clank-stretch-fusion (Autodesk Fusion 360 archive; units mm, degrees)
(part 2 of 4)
sketch "Profile" plane through (3.2, 0, 0) normal (1, 0, 0) x axis (0, 1, 0)
  line L1 (9, 202.17) -> (9, -2.17)
  line L2 (6.5, 202.17) -> (9, 202.17)
  line L3 (6.5, -2.17) -> (6.5, 202.17)
  line L4 (9, -2.17) -> (6.5, -2.17)
  line L5 (8, 15.83) -> (8, 233.17)
  line L6 (6.874, 15.83) -> (6.874, 233.17)
  line L7 (8.254, 233.17) -> (8.254, 15.83)
  line L8 (7.624, 233.17) -> (7.624, 15.83)
  line L9 (7.624, 16.83) -> (6.5, 16.83)
  line L10 (9, 15.83) -> (6.5, 15.83)
  line L11 (8.254, 233.17) -> (6.874, 233.17)
  line L12 (8.154, -2.17) -> (8.154, 31.83)
  line L13 (7.904, -2.17) -> (7.904, 15.83)
  line L14 (14.5, 31.83) -> (8.154, 31.83)
  line L15 (14.5, -2.17) -> (14.5, 31.83)
  line L16 (9, -2.17) -> (14.5, -2.17)
  line L17 (14.5, 217.17) -> (0, 217.17)
  line L18 (0, 217.17) -> (0, 202.17)
  line L19 (6.5, 202.17) -> (0, 202.17)
  line L20 (6.5, 217.17) -> (6.5, 202.17)
  line L21 (14.5, 233.17) -> (14.5, 217.17)
  line L22 (8.154, 233.17) -> (14.5, 233.17)
  line L23 (8.154, 217.17) -> (8.154, 233.17)
  line L24 (0, 233.17) -> (8.154, 233.17)
  line L25 (0, 217.17) -> (0, 233.17)
  line L26 (0, 218.17) -> (7.624, 218.17)
  line L27 (7.624, 251.17) -> (7.624, 233.17)
  line L28 (0, 251.17) -> (7.624, 251.17)
  line L29 (0, 233.17) -> (0, 251.17)
  line L30 (8.154, 251.17) -> (8.154, 233.17)
  line L31 (14.5, 251.17) -> (8.154, 251.17)
  line L32 (14.5, 233.17) -> (14.5, 251.17)
  line L33 (7.874, 251.17) -> (7.874, 217.17)
  line L34 (8.154, 251.17) -> (7.874, 251.17)
  line L35 (0, 216.92) -> (6.5, 216.92)
  arc A1 centre (7.424, 15.83) radius 0.55 clockwise from (6.874, 15.83) to (7.172, 16.3189)
  arc A2 centre (7.6302, 15.43) radius 1 clockwise from (7.172, 16.3189) to (7.4944, 16.4207)
  arc A3 centre (7.474, 16.5693) radius 0.15 clockwise from (7.624, 16.5693) to (7.4944, 16.4207)
  arc A4 centre (7.424, 217.17) radius 0.55 clockwise from (6.874, 217.17) to (7.172, 217.6589)
  arc A5 centre (7.6302, 216.77) radius 1 clockwise from (7.172, 217.6589) to (7.4944, 217.7607)
  arc A6 centre (7.474, 217.9093) radius 0.15 clockwise from (7.624, 217.9093) to (7.4944, 217.7607)
  point P15 (6.874, 15.83)
  point P18 (7.624, 16.5693)
  point P22 (6.5, 16.83)
  point P23 (7.624, 16.83)
  point P24 (6.5, 15.83)
  point P25 (9, 15.83)
  point P10 (6.874, 15.83)
  point P13 (7.424, 15.83)
  point P20 (7.624, 15.83)
  point P7 (8, 15.83)
  point P11 (8.254, 15.83)
  point P12 (8.254, 233.17)
  point P26 (8.254, 233.17)
  point P6 (8, 233.17)
  point P21 (7.624, 233.17)
  point P29 (7.904, 15.83)
  point P30 (7.904, -2.17)
  point P2 (9, -2.17)
  point P33 (9, -2.17)
  point P28 (8.154, -2.17)
  point P27 (8.154, 31.83)
  point P36 (8.154, 31.83)
  point P37 (0, 202.17)
  point P38 (0, 202.17)
  point P40 (0, 202.17)
  point P4 (6.5, 202.17)
  point P41 (6.5, 202.17)
  point P42 (6.5, 217.17)
  point P34 (0, 217.17)
  point P39 (0, 217.17)
  point P45 (8.154, 217.17)
  point P47 (0, 217.17)
  point P31 (14.5, 31.83)
  point P53 (6.874, 217.17)
  point P52 (7.424, 217.17)
  point P49 (7.624, 217.9093)
  point P55 (7.624, 218.17)
  point P56 (0, 218.17)
  point P46 (0, 233.17)
  point P59 (0, 233.17)
  point P43 (14.5, 233.17)
  point P62 (14.5, 233.17)
  point P60 (8.154, 251.17)
  point P63 (7.874, 217.17)
  point P65 (6.5, 216.92)
  point P66 (0, 216.92)
  point P16 (7.6302, 15.43)
  point P32 (14.5, -2.17)
  point P3 (9, 202.17)
  point P48 (7.6302, 216.77)
  point P61 (14.5, 251.17)
  point P57 (7.624, 251.17)
  point P64 (7.874, 251.17)
  perpendicular L4 L5
  perpendicular L4 L6
  perpendicular L4 L7
  coincident L6 P15
  tangent A1 A2
  tangent A2 A3
  vertical L8
  coincident P18 L8
  tangent A3 L8
  coincident L3 P22
  coincident L8 P23
  perpendicular L8 L9
  coincident L3 P24
  coincident L1 P25
  perpendicular L1 L10
  coincident P10 L10
  coincident P15 L10
  coincident P13 L10
  coincident P20 L10
  coincident P7 L10
  coincident P11 L10
  perpendicular L5 L11
  coincident P12 P26
  coincident P6 L11
  coincident P21 L11
  perpendicular L10 L12
  coincident L10 P29
  coincident L4 P30
  perpendicular L4 L13
  perpendicular L7 L14
  perpendicular L14 L15
  perpendicular L15 L16
  coincident P2 P33
  coincident L4 P28
  horizontal L17
  coincident P27 P36
  coincident P37 P38
  parallel L8 L18
  coincident P37 P40
  coincident P4 P41
  perpendicular L19 L20
  coincident L17 P42
  coincident P34 P39
  perpendicular L17 L21
  perpendicular L21 L22
  coincident L17 P45
  perpendicular L17 L23
  perpendicular L8 L24
  perpendicular L24 L25
  coincident P39 P47
  coincident P31 L21
  coincident P12 L22
  coincident P27 L23
  tangent A4 A5
  tangent A5 A6
  coincident L17 P53
  coincident L17 P52
  coincident L8 P49
  coincident L6 P53
  tangent L8 A6
  coincident L8 P55
  coincident L25 P56
  perpendicular L25 L26
  perpendicular L24 L27
  perpendicular L27 L28
  perpendicular L28 L29
  coincident P46 P59
  perpendicular L22 L30
  perpendicular L30 L31
  perpendicular L22 L32
  coincident P43 P62
  coincident L28 P60
  coincident L17 P63
  perpendicular L31 L33
  perpendicular L30 L34
  coincident L20 P65
  coincident L18 P66
  perpendicular L18 L35
  dimension "d100" distance L1 L5 = 1
  dimension "d102" distance P7 P11 = 0.254
  dimension "d103" distance P10 P11 = 1.38
  dimension "d104" radius A1 = 0.55
  dimension "d106" radius A2 = 1
  dimension "d107" radius A3 = 0.15
  dimension "d109" distance L6 P21 = 0.75
  dimension "d110" distance P13 L9 = 1
  dimension "d149" distance P16 L10 = 0.4
  dimension "d150" distance P2 L10 = 18
  dimension "d155" distance P11 L12 = 0.1
  dimension "d156" distance P32 P33 = 5.5
  dimension "d174" distance P28 L13 = 0.25
  dimension "d175" distance P28 L15 = 6.346
  dimension "d179" distance P3 L17 = 15
  dimension "d180" distance P25 L14 = 16
  dimension "d190" distance P12 L17 = 16
  dimension "d193" radius A4 = 0.55
  dimension "d194" radius A5 = 1
  dimension "d195" radius A6 = 0.15
  dimension "d196" distance L17 P48 = 0.4
  dimension "d197" distance P53 L26 = 1
  dimension "d225" distance P61 P62 = 18
  dimension "d250" distance P57 P64 = 0.25
  dimension "d261" distance P47 L35 = 0.25
extrude "Extrude12" new body sketch "Profile" profile of L3 A1 A2 A3 L8 L9 to an object
mirror "Mirror3" mirrorStitchTolerance 0.1
rectangular_pattern "R-Pattern1" uSpaceDistance 2 vSpaceDistance 0
combine "Combine1"
extrude "Extrude15" add sketch "Profile" profile of L3 L4 L10 L13 to an object
extrude "Extrude16" new body sketch "Profile" profile of L1 L4 L10 L12 L14 L15 L16 to an object offset -0.25 from offset 0.25 bodies "XZ Lower Clamp"
chamfer "Chamfer1" distance 2.5
chamfer "Chamfer9" distance 12 distance 3
sketch "Lower Pinch Nuts" plane through (0, 14.5, 0) normal (0, 1, 0) x axis (-1, 0, 0)
  line L1 (-14.95, -2.17) -> (-14.95, 19.83)
  line L2 (-5.95, -2.17) -> (-14.95, -2.17)
  line L3 (-5.95, 19.83) -> (-5.95, -2.17)
  line L4 (-6.4085, 11.83) -> (-8.4293, 8.33)
  line L5 (-8.4293, 15.33) -> (-6.4085, 11.83)
  line L6 (-12.4707, 15.33) -> (-8.4293, 15.33)
  line L7 (-14.4915, 11.83) -> (-12.4707, 15.33)
  line L8 (-12.4707, 8.33) -> (-14.4915, 11.83)
  line L9 (-8.4293, 8.33) -> (-12.4707, 8.33)
  line L10 (-6.4085, 2.83) -> (-8.4293, -0.67)
  line L11 (-8.4293, 6.33) -> (-6.4085, 2.83)
  line L12 (-12.4707, 6.33) -> (-8.4293, 6.33)
  line L13 (-14.4915, 2.83) -> (-12.4707, 6.33)
  line L14 (-12.4707, -0.67) -> (-14.4915, 2.83)
  line L15 (-8.4293, -0.67) -> (-12.4707, -0.67)
  line L16 (-10.45, 2.83) -> (-10.45, -2.17)
  line L17 (-10.45, 2.83) -> (-10.45, 11.83)
  line L18 (-14.95, 19.83) -> (-5.95, 19.83)
  circle C1 centre (-10.45, 11.83) radius 2.125
  circle C2 centre (-10.45, 2.83) radius 2.125
  circle C3 centre (-10.45, 11.83) radius 4.125
  circle C4 centre (-10.45, 2.83) radius 4.125
  point P6 (-10.45, 11.83)
  point P13 (-10.45, 11.83)
  point P20 (-10.45, 2.83)
  point P21 (-10.45, 2.83)
  point P22 (-10.45, -2.17)
  point P23 (-10.45, 2.83)
  point P24 (-10.45, 11.83)
  point P25 (-10.45, 2.83)
  point P26 (-10.45, 11.83)
  point P14 (-8.4293, -0.67)
  coincident P6 P13
  coincident P20 P21
  midpoint L2 P22
  coincident P21 P23
  vertical L16
  horizontal L15
  equal C1 C2
  equal L9 L15
  horizontal L9
  coincident P6 P24
  coincident P20 P25
  vertical L17
  coincident P13 P26
  concentric C2 C4
  equal C3 C4
  dimension "d163" distance P14 L12 = 7
  dimension "d164" diameter C2 = 4.25
  dimension "d165" distance P22 P23 = 5
  dimension "d166" distance P24 P25 = 9
  dimension "d177" diameter C3 = 8.25
extrude "Extrude17" cut sketch "Lower Pinch Nuts" profile of C1 C2 to an object
extrude "Extrude19" cut sketch "Lower Pinch Nuts" profile of C1 L4 L5 L6 L7 L8 L9 L10 L11 L12 L13 L14 L15 C2 against normal blind 5.2
chamfer "Chamfer2" distance 0.4
chamfer "Chamfer3" distance 2.5
extrude "Extrude21" sketch "Profile" profile of L8 L17 L25 A4 A5 A6 L26 to an object bodies "XZ Upper Clamp Front"
mirror "Mirror4" mirrorStitchTolerance 0.1
rectangular_pattern "R-Pattern2" uSpaceDistance 2 vSpaceDistance 0
combine "Combine2"
extrude "Extrude28" add sketch "Profile" profile of L24 L27 L28 L29 to an object
extrude "Extrude29" new body sketch "Profile" profile of L17 L21 L22 L23 L24 L30 L31 L32 L33 L34 to an object bodies "XZ Upper Clamp Rear"
sketch "Sketch6" plane through (0, 14.5, 0) normal (0, 1, 0) x axis (-1, 0, 0)
  line L1 (-17.7, 217.17) -> (-17.7, 251.17)
  line L2 (-3.2, 217.17) -> (-17.7, 217.17)
  line L3 (-3.2, 251.17) -> (-3.2, 217.17)
  line L4 (-17.7, 251.17) -> (-3.2, 251.17)
  line L5 (-8.4293, 242.67) -> (-12.4707, 242.67)
  line L6 (-12.4707, 242.67) -> (-14.4915, 246.17)
  line L7 (-8.4293, 233.67) -> (-12.4707, 233.67)
  line L8 (-12.4707, 233.67) -> (-14.4915, 237.17)
  line L9 (-12.4707, 240.67) -> (-8.4293, 240.67)
  line L10 (-8.4293, 249.67) -> (-6.4085, 246.17)
  line L11 (-14.4915, 237.17) -> (-12.4707, 240.67)
  line L12 (-6.4085, 237.17) -> (-8.4293, 233.67)
  line L13 (-8.4293, 240.67) -> (-6.4085, 237.17)
  line L14 (-14.4915, 246.17) -> (-12.4707, 249.67)
  line L15 (-6.4085, 246.17) -> (-8.4293, 242.67)
  line L16 (-12.4707, 249.67) -> (-8.4293, 249.67)
  line L17 (-10.45, 237.17) -> (-10.45, 246.17)
  line L18 (-10.45, 251.17) -> (-10.45, 246.17)
  circle C1 centre (-10.45, 237.17) radius 4.125
  circle C2 centre (-10.45, 237.17) radius 2.125
  circle C3 centre (-10.45, 246.17) radius 4.125
  circle C4 centre (-10.45, 246.17) radius 2.125
  point P6 (-10.45, 246.17)
  point P12 (-10.45, 246.17)
  point P16 (-10.45, 237.17)
  point P24 (-10.45, 237.17)
  point P25 (-10.45, 237.17)
  point P26 (-10.45, 246.17)
  point P23 (-10.45, 237.17)
  point P15 (-10.45, 246.17)
  point P27 (-10.45, 246.17)
  point P28 (-10.45, 251.17)
  point P19 (-8.4293, 233.67)
  coincident P6 P12
  coincident P16 P24
  coincident P24 P25
  horizontal L7
  equal C2 C4
  equal L5 L7
  horizontal L5
  coincident P6 P26
  coincident P16 P23
  vertical L17
  coincident P12 P15
  concentric C1 C2
  equal C1 C3
  coincident P15 P27
  midpoint L4 P28
  vertical L18
  dimension "d230" distance P19 L9 = 7
  dimension "d231" diameter C2 = 4.25
  dimension "d232" distance P23 P26 = 9
  dimension "d233" diameter C3 = 8.25
  dimension "d234" distance P27 P28 = 5
extrude "Extrude30" cut sketch "Sketch6" profile of C2 C4 to an object
extrude "Extrude31" cut sketch "Sketch6" profile of L5 L6 L7 L8 L9 L10 C2 L11 C4 L12 L13 L14 L15 L16 to an object
chamfer "Chamfer5" distance 2.25
chamfer "Chamfer6" distance 0.5
extrude "Extrude32" sketch "Profile" profile of L8 L17 L21 L22 L23 L24 L25 A4 A5 A6 L26 L27 L28 L29 L30 L31 L32 L33 L34 blind 9
extrude "Extrude33" add sketch "Profile" profile of L8 L17 L21 L22 L23 L24 L25 A4 A5 A6 L26 L27 L28 L29 L30 L31 L32 L33 L34 against normal blind 9
sketch "Sketch7" plane through (0, 0, 251.17) normal (0, 0, 1) x axis (-1, 0, 0)
  line L1 (5.8, -7.624) -> (-26.7, -7.624)
  line L2 (5.8, 0) -> (5.8, -7.624)
  line L3 (-26.7, 0) -> (5.8, 0)
  line L4 (-26.7, -7.624) -> (-26.7, 0)
  line L5 (-21.45, -3.5825) -> (-17.95, -5.6033)
  line L6 (-24.95, -5.6033) -> (-21.45, -3.5825)
  line L7 (-24.95, -9.6447) -> (-24.95, -5.6033)
  line L8 (-21.45, -11.6655) -> (-24.95, -9.6447)
  line L9 (-17.95, -9.6447) -> (-21.45, -11.6655)
  line L10 (-17.95, -5.6033) -> (-17.95, -9.6447)
  line L11 (-10.45, -7.624) -> (-10.45, 0)
  line L12 (4.05, -9.6447) -> (4.05, -5.6033)
  line L13 (0.55, -11.6655) -> (4.05, -9.6447)
  line L14 (-2.95, -9.6447) -> (0.55, -11.6655)
  line L15 (-2.95, -5.6033) -> (-2.95, -9.6447)
  line L16 (4.05, -5.6033) -> (0.55, -3.5825)
  line L17 (0.55, -3.5825) -> (-2.95, -5.6033)
  line L18 (-3.2, -9) -> (-3.2, -6.5)
  line L19 (-17.7, -6.5) -> (-17.7, -9)
  line L20 (-17.7, 0) -> (-17.7, -6.5)
  line L21 (-17.7, -14.5) -> (-17.7, -9)
  line L22 (5.8, -14.5) -> (-26.7, -14.5)
  line L23 (5.8, -7.874) -> (5.8, -14.5)
  line L24 (-26.7, -7.874) -> (5.8, -7.874)
  line L25 (-26.7, -14.5) -> (-26.7, -7.874)
  line L26 (-3.2, 0) -> (-3.2, -6.5)
  line L27 (-3.2, -14.5) -> (-3.2, -9)
  line L28 (5.8, -7.624) -> (5.8, -7.874)
  circle C1 centre (-21.45, -7.624) radius 2.125
  circle C2 centre (0.55, -7.624) radius 2.125
  point P6 (-21.45, -7.624)
  point P13 (-21.45, -7.624)
  point P14 (-10.45, 0)
  point P15 (-10.45, 0)
  point P16 (-10.45, -7.624)
  point P7 (-17.95, -5.6033)
  point P22 (-2.95, -5.6033)
  point P8 (-21.45, -3.5825)
  point P23 (0.55, -3.5825)
  point P9 (-24.95, -5.6033)
  point P18 (4.05, -5.6033)
  point P10 (-24.95, -9.6447)
  point P19 (4.05, -9.6447)
  point P11 (-21.45, -11.6655)
  point P20 (0.55, -11.6655)
  point P12 (-17.95, -9.6447)
  point P21 (-2.95, -9.6447)
  point P27 (-17.7, -6.5)
  point P28 (-17.7, -6.5)
  point P29 (-17.7, 0)
  point P26 (-17.7, -9)
  point P30 (-17.7, -9)
  point P31 (-17.7, -14.5)
  point P24 (-3.2, -6.5)
  point P36 (-3.2, -6.5)
  point P37 (-3.2, 0)
  point P25 (-3.2, -9)
  point P38 (-3.2, -9)
  point P39 (-3.2, -14.5)
  point P34 (5.8, -7.874)
  point P40 (5.8, -7.874)
  point P3 (5.8, -7.624)
  point P41 (5.8, -7.624)
  coincident L1 P6
  coincident P6 P13
  vertical L7
  midpoint L3 P14
  coincident P14 P15
  midpoint L1 P16
  symmetric C1 L11 C2
  symmetric P7 L11 P22
  symmetric P8 L11 P23
  symmetric P9 L11 P18
  symmetric P10 L11 P19
  symmetric P11 L11 P20
  symmetric P12 L11 P21
  coincident P27 P28
  coincident L3 P29
  perpendicular L3 L20
  coincident P26 P30
  parallel L10 L21
  coincident P31 L22
  coincident P24 P36
  coincident L3 P37
  perpendicular L3 L26
  coincident P25 P38
  coincident L22 P39
  perpendicular L22 L27
  coincident P34 P40
  coincident P3 P41
  dimension "d246" diameter C1 = 4.25
  dimension "d247" distance P12 L7 = 7
  dimension "d248" distance P6 P14 = 11
extrude "Extrude34" cut sketch "Sketch7" profile of L1 C1 C2 to an object
extrude "Extrude35" cut sketch "Sketch7" profile of L1 C1 L5 L6 L7 L8 L9 L10 C2 L12 L13 L14 L15 L16 L17 blind -5.5 from offset -8
extrude "Extrude36" sketch "Sketch7" profile of L1 L2 L3 L4 C1 L5 L6 L7 L8 L9 L10 C2 L12 L13 L14 L15 L16 L17 L18 L19 L20 L21 L22 L23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 blind 16
fillet "Fillet5" radius 2
fillet "Fillet6" radius 0.5
extrude "Extrude37" add sketch "Profile" profile of L18 L19 L20 L35 to an object
extrude "Extrude38" add sketch "Profile" profile of L18 L19 L20 L35 to an object
extrude "Extrude39" sketch "Profile" profile of L18 L19 L20 L35 to an object
sketch "Sketch8" plane through (0, 6.5, 0) normal (0, 1, 0) x axis (-1, 0, 0)
  line L1 (-3.2, 31.83) -> (-17.7, 31.83)
  line L2 (-3.2, 202.17) -> (-3.2, 31.83)
  line L3 (5.8, 202.17) -> (-3.2, 202.17)
  line L4 (5.8, 216.92) -> (5.8, 202.17)
  line L5 (-26.7, 216.92) -> (5.8, 216.92)
  line L6 (-26.7, 202.17) -> (-26.7, 216.92)
  line L7 (-17.7, 202.17) -> (-26.7, 202.17)
  line L8 (-17.7, 31.83) -> (-17.7, 202.17)
  line L9 (-2.95, 232.92) -> (-2.95, 202.17)
  line L10 (5.8, 232.92) -> (-2.95, 232.92)
  line L11 (5.8, 216.92) -> (5.8, 232.92)
  line L12 (-17.95, 232.92) -> (-17.95, 202.17)
  line L13 (-26.7, 232.92) -> (-17.95, 232.92)
  line L14 (-26.7, 216.92) -> (-26.7, 232.92)
  point P10 (-2.95, 202.17)
  point P6 (5.8, 216.92)
  point P13 (5.8, 216.92)
  point P14 (-17.95, 202.17)
  point P7 (-26.7, 216.92)
  point P17 (-26.7, 216.92)
  point P11 (-2.95, 232.92)
  point P18 (-3.2, 233.17)
  point P4 (-3.2, 202.17)
  point P9 (-17.7, 202.17)
  coincident L3 P10
  perpendicular L3 L9
  perpendicular L9 L10
  perpendicular L3 L11
  coincident P6 P13
  coincident L7 P14
  perpendicular L5 L12
  perpendicular L12 L13
  perpendicular L13 L14
  coincident P7 P17
  coincident P11 L13
  dimension "d271" distance L10 P18 = 0.25
  dimension "d272" distance P4 L9 = 0.25
  dimension "d273" distance P9 L12 = 0.25
extrude "Extrude40" add sketch "Sketch8" profile of L5 L9 L10 L11 L12 L13 L14 to an object
extrude "Extrude41" add sketch "Sketch8" profile of L5 L9 L10 L11 L12 L13 L14 to an object
extrude "Extrude42" add sketch "Sketch8" profile of L3 L4 L5 L6 L7 L9 L12 to an object
extrude "Extrude43" add of existing geometry to an object
fillet "Fillet7" radius 5
sketch "Sketch9" plane through (0, 14.5, 0) normal (0, 1, 0) x axis (-1, 0, 0)
  line L1 (-17.95, 232.92) -> (-17.95, 216.92)
  line L2 (-26.7, 232.92) -> (-17.95, 232.92)
  line L3 (-26.7, 216.92) -> (-26.7, 232.92)
  line L4 (5.8, 232.92) -> (5.8, 216.92)
  line L5 (-2.95, 232.92) -> (5.8, 232.92)
  line L6 (-2.95, 216.92) -> (-2.95, 232.92)
  line L7 (-2.95, 232.92) -> (-17.95, 232.92)
  line L8 (-10.45, 222.92) -> (-10.45, 232.92)
  line L9 (-21.45, 230.42) -> (-21.45, 251.17)
  line L10 (-22.8289, 231.7989) -> (-23.95, 232.92)
  line L11 (-18.95, 232.92) -> (-20.0711, 231.7989)
  line L12 (-1.95, 232.92) -> (-0.8289, 231.7989)
  line L13 (1.9289, 231.7989) -> (3.05, 232.92)
  line L14 (-17.95, 216.92) -> (-26.7, 216.92)
  line L15 (5.8, 216.92) -> (-2.95, 216.92)
  circle C1 centre (-21.45, 230.42) radius 1.95
  circle C2 centre (0.55, 230.42) radius 1.95
  point P4 (-17.95, 232.92)
  point P10 (-17.95, 232.92)
  point P9 (-2.95, 232.92)
  point P11 (-2.95, 232.92)
  point P12 (-10.45, 232.92)
  point P15 (-21.45, 251.17)
  point P16 (-21.45, 251.17)
  point P14 (-21.45, 230.42)
  point P17 (-21.45, 230.42)
  point P19 (-23.95, 232.92)
  point P20 (-22.8289, 231.7989)
  point P21 (-20.0711, 231.7989)
  point P22 (-18.95, 232.92)
  point P25 (3.05, 232.92)
  point P26 (1.9289, 231.7989)
  point P23 (-0.8289, 231.7989)
  point P24 (-1.95, 232.92)
  coincident P4 P10
  coincident P9 P11
  midpoint L7 P12
  perpendicular L7 L8
  coincident P15 P16
  coincident P14 P17
  vertical L9
  symmetric L8 C1 C2
  coincident L2 P19
  coincident C1 P20
  coincident P14 L10
  coincident C1 P21
  coincident L2 P22
  coincident P14 L11
  symmetric L8 P19 P25
  symmetric L8 P20 P26
  symmetric L8 P21 P23
  symmetric L8 P22 P24
  dimension "d285" diameter C1 = 3.9
  dimension "d286" distance L2 P14 = 2.5
  dimension "d289" angle L9 L10 = 45
  dimension "d290" angle L9 L11 = 45
extrude "Extrude44" cut sketch "Sketch9" profile of C1 C2 to an object
extrude "Extrude45" sketch "Sketch9" profile of L2 L5 C1 C2 L10 L11 L12 L13 blind 3.5
chamfer "Chamfer8" distance 1
fillet "Fillet10" radius 0.5
sketch "Sketch10" plane through (0, 9, 0) normal (0, 1, 0) x axis (-1, 0, 0)
  line L1 (-3.2, -2.17) -> (-3.2, 202.17)
  line L2 (29.8824, -2.17) -> (-3.2, -2.17)
  line L3 (29.8824, -0.5) -> (29.8824, -2.17)
  line L4 (29.8824, 200.5) -> (29.8824, -0.5)
  line L5 (29.8824, 202.17) -> (29.8824, 200.5)
  line L6 (10.8, 202.17) -> (29.8824, 202.17)
  line L7 (-2.95, 202.17) -> (-2.95, 216.92)
  line L8 (-3.2, 202.17) -> (-2.95, 202.17)
  line L9 (7.5, 89.8507) -> (7.5, 85.8093)
  line L10 (11, 91.8715) -> (7.5, 89.8507)
  line L11 (14.5, 89.8507) -> (11, 91.8715)
  line L12 (14.5, 85.8093) -> (14.5, 89.8507)
  line L13 (11, 83.7885) -> (14.5, 85.8093)
  line L14 (7.5, 85.8093) -> (11, 83.7885)
  line L15 (5, 63.8715) -> (1.5, 61.8507)
  line L16 (8.5, 61.8507) -> (5, 63.8715)
  line L17 (8.5, 57.8093) -> (8.5, 61.8507)
  line L18 (5, 55.7885) -> (8.5, 57.8093)
  line L19 (1.5, 57.8093) -> (5, 55.7885)
  line L20 (1.5, 61.8507) -> (1.5, 57.8093)
  line L21 (15, 9.8715) -> (11.5, 7.8507)
  line L22 (18.5, 7.8507) -> (15, 9.8715)
  line L23 (18.5, 3.8093) -> (18.5, 7.8507)
  line L24 (15, 1.7885) -> (18.5, 3.8093)
  line L25 (11.5, 3.8093) -> (15, 1.7885)
  line L26 (11.5, 7.8507) -> (11.5, 3.8093)
  line L27 (10, 108.8715) -> (6.5, 106.8507)
  line L28 (13.5, 106.8507) -> (10, 108.8715)
  line L29 (13.5, 102.8093) -> (13.5, 106.8507)
  line L30 (10, 100.7885) -> (13.5, 102.8093)
  line L31 (6.5, 102.8093) -> (10, 100.7885)
  line L32 (6.5, 106.8507) -> (6.5, 102.8093)
  line L33 (-2.95, 216.92) -> (5.8, 216.92)
  line L34 (5.8, 216.92) -> (5.8, 207.17)
  line L35 (-1.5, 171.8093) -> (2, 169.7885)
  line L36 (-1.5, 175.8507) -> (-1.5, 171.8093)
  line L37 (2, 177.8715) -> (-1.5, 175.8507)
  line L38 (5.5, 175.8507) -> (2, 177.8715)
  line L39 (5.5, 171.8093) -> (5.5, 175.8507)
  line L40 (2, 169.7885) -> (5.5, 171.8093)
  arc A1 centre (10.8, 207.17) radius 5 clockwise from (10.8, 202.17) to (5.8, 207.17)
  circle C1 centre (7.1324, 126.17) radius 1.85
  circle C2 centre (7.1324, 126.17) radius 4.25
  point P8 (10.8, 202.17)
  point P37 (7.1324, 126.17)
  point P7 (29.8824, 202.17)
  concentric C1 C2
  dimension "d301" distance P8 P37 = 76 (= "26 mm + 50 mm")
  dimension "d302" diameter C1 = 3.7
  dimension "d303" distance P7 P37 = 22.75
  dimension "d310" diameter C2 = 8.5
extrude "Extrude46" cut sketch "Sketch10" profile of C1 to an object
extrude "Extrude47" cut sketch "Sketch10" profile of C1 C2 against normal blind 1
component_from_bodies "Body->Comp1"
component_from_bodies "Body->Comp2"
component_from_bodies "Body->Comp3"
component_from_bodies "Body->Comp4"
as_built_joint "As-built1"
as_built_joint "As-built2"
as_built_joint "As-built3"
as_built_joint "As-built4"
component_insert "Component Insert29"
joint "Assemble28" alignAngle 0 alignOffsetX 0 alignOffsetY 0 alignOffsetZ 0
component_insert "Component Insert30"
joint "Assemble29" alignAngle 0 alignOffsetX 0 alignOffsetY 0 alignOffsetZ 0
component_insert "Component Insert1"
joint "Assemble30" alignAngle 0 alignOffsetX 0 alignOffsetY 0 alignOffsetZ 0
component_insert "Component Insert5"
joint "Assemble31" alignAngle -30 alignOffsetX 0 alignOffsetY 0 alignOffsetZ 0
component_insert "Component Insert6"
joint "Assemble32" alignAngle -30 alignOffsetX 0 alignOffsetY 0 alignOffsetZ 0
component_insert "Component Insert7"
joint "Assemble33" alignAngle 0 alignOffsetX 0 alignOffsetY 0 alignOffsetZ 0
component_insert "Component Insert8"
joint "Assemble34" alignAngle 0 alignOffsetX 0 alignOffsetY 0 alignOffsetZ 0
component_insert "Component Insert31"
joint "Assemble35" alignAngle 0 alignOffsetX 0 alignOffsetY 0 alignOffsetZ 0
component_insert "Component Insert32"
joint "Assemble36" alignAngle 0 alignOffsetX 0 alignOffsetY 0 alignOffsetZ 0
component_insert "Component Insert33"
joint "Assemble37" alignAngle 0 alignOffsetX 0 alignOffsetY 0 alignOffsetZ 0
component_insert "Component Insert34"
joint "Assemble38" alignAngle 0 alignOffsetX 0 alignOffsetY 0 alignOffsetZ 0
component_insert "Component Insert35"
joint "Assemble39" alignAngle 0 alignOffsetX 0 alignOffsetY 0 alignOffsetZ 0
component_insert "Component Insert36"
joint "Assemble40" alignAngle 0 alignOffsetX 0 alignOffsetY 0 alignOffsetZ 0
component_insert "Component Insert37"
joint "Assemble41" alignAngle 0 alignOffsetX 0 alignOffsetY 0 alignOffsetZ 0
component_insert "Component Insert38"
joint "Assemble42" alignAngle -30 alignOffsetX 0 alignOffsetY 0 alignOffsetZ 0
component_insert "Component Insert39"
joint "Assemble43" alignAngle -30 alignOffsetX 0 alignOffsetY 0 alignOffsetZ 0
component_insert "Component Insert40"
joint "Assemble44" alignAngle 0 alignOffsetX 0 alignOffsetY 0 alignOffsetZ 0
component_insert "Component Insert41"
joint "Assemble45" alignAngle 0 alignOffsetX 0 alignOffsetY 0 alignOffsetZ 0
component_insert "Component Insert42"
joint "Assemble46" alignAngle 0 alignOffsetX 0 alignOffsetY 0 alignOffsetZ 0
component_insert "Component Insert43"
joint "Assemble47" alignAngle 0 alignOffsetX 0 alignOffsetY 0 alignOffsetZ 0
component_insert "Component Insert44"
joint "Assemble48" alignAngle 0 alignOffsetX 0 alignOffsetY 0 alignOffsetZ 0
component_insert "Component Insert45"
joint "Assemble49" alignAngle 0 alignOffsetX 0 alignOffsetY 0 alignOffsetZ 0
component_insert "Component Insert46"
joint "Assemble50" alignAngle 0 alignOffsetX 0 alignOffsetY 0 alignOffsetZ 0
component_insert "Component Insert47"
joint "Assemble51" alignAngle 0 alignOffsetX 0 alignOffsetY 0 alignOffsetZ -8
component_insert "Component Insert48"
joint "Assemble52" alignAngle 0 alignOffsetX 0 alignOffsetY 0 alignOffsetZ -8
component_insert "Component Insert49"
joint "Assemble53" alignAngle 0 alignOffsetX 0 alignOffsetY 0 alignOffsetZ 0
component_insert "Component Insert50"
joint "Assemble54" alignAngle 0 alignOffsetX 0 alignOffsetY 0 alignOffsetZ 0
component_insert "Component Insert51"
joint "Assemble55" alignAngle 0 alignOffsetX 0 alignOffsetY 0 alignOffsetZ 0
component_insert "Component Insert52"
joint "Assemble56" alignAngle 0 alignOffsetX 0 alignOffsetY 0 alignOffsetZ 0
component_insert "Component Insert53"
joint "Assemble57" alignAngle 0 alignOffsetX 0 alignOffsetY 0 alignOffsetZ 0
component_insert "Component Insert54"
joint "Assemble58" alignAngle 0 alignOffsetX 0 alignOffsetY 0 alignOffsetZ 0
component_insert "Component Insert55"
joint "Assemble59" alignAngle 0 alignOffsetX 0 alignOffsetY 0 alignOffsetZ 0
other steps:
base_feature "Base Feature1" bodies "XZ Lower Clamp"
base_feature "Base Feature1" bodies "XZ Upper Clamp Front"
base_feature "Base Feature1" bodies "XZ Upper Clamp Rear"
base_feature "Base Feature1" bodies "XZ Interposer"
create_component "CreateComponent1"
remove_body "RemoveBody1"
create_component "CreateComponent2"
remove_body "RemoveBody2"
create_component "CreateComponent3"
remove_body "RemoveBody3"
create_component "CreateComponent4"
remove_body "RemoveBody4"
joint_origin "JointOrigin1"
joint_origin "JointOrigin2"
joint_origin "JointOrigin3"
joint_origin "JointOrigin1"
joint_origin "JointOrigin2"
joint_origin "JointOrigin4"
joint_origin "JointOrigin5"
joint_origin "JointOrigin6"
joint_origin "JointOrigin7"
joint_origin "JointOrigin8"
joint_origin "JointOrigin9"
joint_origin "JointOrigin10"
joint_origin "JointOrigin11"
joint_origin "JointOrigin12"
joint_origin "JointOrigin1"
joint_origin "JointOrigin2"
joint_origin "JointOrigin3"
joint_origin "JointOrigin4"
joint_origin "JointOrigin13"
joint_origin "JointOrigin14"
joint_origin "JointOrigin15"
joint_origin "JointOrigin1"
joint_origin "JointOrigin2"
joint_origin "JointOrigin3"
joint_origin "JointOrigin4"
named bodies: "XZ Interposer", "XZ Lower Clamp", "XZ Upper Clamp Front", "XZ Upper Clamp Rear"

design "HW_M2x12-SHCS"
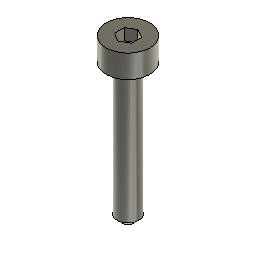
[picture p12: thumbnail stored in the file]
sketch "Sketch1" plane through (0, 0, 0) normal (0, 1, 0) x axis (1, 0, 0)
  line L1 (0, 12) -> (0, -2)
  line L2 (0.45, 12) -> (0, 12)
  line L3 (0.95, 11.5) -> (0.45, 12)
  line L4 (0.95, 0) -> (0.95, 11.5)
  line L5 (1.9, 0) -> (0.95, 0)
  line L6 (1.9, -2) -> (1.9, 0)
  line L7 (0, -2) -> (1.9, -2)
  point P1 (0, 0)
  point P4 (0.45, 12)
  point P5 (0.95, 11.5)
  point P3 (0, 12)
  point P7 (1.9, 0)
  point P8 (1.9, -2)
  point P2 (0, -2)
  vertical L1
  perpendicular L1 L2
  perpendicular L2 L4
  perpendicular L4 L5
  perpendicular L5 L6
  horizontal L7
  coincident P1 L1
  coincident P1 L5
  dimension "d1" distance P1 L2 = 12
  dimension "d2" angle L2 L3 = 45
  dimension "d3" distance P4 P5 = 0.5
  dimension "d4" distance P3 L4 = 0.95 (= "( 1.9 / 2 ) * 1 mm")
  dimension "d5" distance P7 P8 = 2
  dimension "d6" distance P2 P8 = 1.9 (= "( 3.8 / 2 ) * 1 mm")
revolve "Revolve1" sketch "Sketch1" AlongAngle 360
sketch "Sketch2" plane through (0, 0, 2) normal (0, 0, 1) x axis (-1, 0, 0)
  line L1 (0, -0.866) -> (-0.75, -0.433)
  line L2 (0.75, -0.433) -> (0, -0.866)
  line L3 (0.75, 0.433) -> (0.75, -0.433)
  line L4 (0, 0.866) -> (0.75, 0.433)
  line L5 (-0.75, 0.433) -> (0, 0.866)
  line L6 (-0.75, -0.433) -> (-0.75, 0.433)
  circle C1 centre (0, 0) radius 1.9
  point P1 (0, 0)
  point P9 (0, 0)
  point P5 (0.75, -0.433)
  coincident P1 P9
  vertical L6
  dimension "d8" distance P5 L6 = 1.5
extrude "Extrude1" cut sketch "Sketch2" profile of L1 L2 L3 L4 L5 L6 against normal blind 1

design "HW_M4-Nylock"
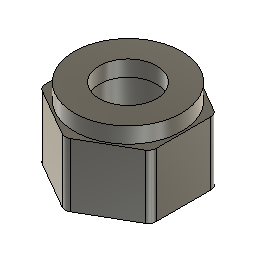
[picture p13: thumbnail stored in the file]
sketch "Sketch1" plane through (0, 0, 0) normal (0, 0, 1) x axis (1, 0, 0)
  line L1 (0, 4.0415) -> (3.5, 2.0207)
  line L2 (-3.5, 2.0207) -> (0, 4.0415)
  line L3 (-3.5, -2.0207) -> (-3.5, 2.0207)
  line L4 (0, -4.0415) -> (-3.5, -2.0207)
  line L5 (3.5, -2.0207) -> (0, -4.0415)
  line L6 (3.5, 2.0207) -> (3.5, -2.0207)
  circle C1 centre (0, 0) radius 2.05
  circle C2 centre (0, 0) radius 3.375
  circle C3 centre (0, 0) radius 1.8
  point P1 (0, 0)
  point P8 (0, 0)
  point P9 (0, 0)
  point P4 (-3.5, 2.0207)
  coincident P1 P8
  vertical L6
  coincident P8 P9
  concentric C1 C2
  concentric C1 C3
  dimension "d1" distance P4 L6 = 7
  dimension "d2" diameter C1 = 4.1
  dimension "d5" diameter C2 = 6.75 (= "d1 - 0.25 mm")
  dimension "d9" distance C1 C3 = 0.25
extrude "Extrude1" new body sketch "Sketch1" profile of L1 L2 L3 L4 L5 L6 C1 C2 along normal blind 4
extrude "Extrude2" sketch "Sketch1" profile of C1 C2 C3 blind 1
fillet "Fillet1" radius 0.5

design "CT_UCBus-3010"
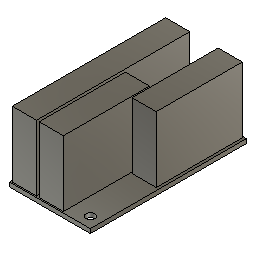
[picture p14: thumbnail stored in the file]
sketch "Sketch1" plane through (0, 0, 0) normal (0, 0, 1) x axis (1, 0, 0)
  line L1 (30, 0) -> (0, 0)
  line L2 (30, 58) -> (30, 0)
  line L3 (0, 0) -> (0, 58)
  line L4 (9.5, 57.5) -> (0.5, 57.5)
  line L5 (9.5, 0.5) -> (9.5, 57.5)
  line L6 (0.5, 0.5) -> (9.5, 0.5)
  line L7 (0.5, 57.5) -> (0.5, 0.5)
  line L8 (0, 58) -> (30, 58)
  line L9 (7.5, 48) -> (2.5, 48)
  line L10 (7.5, 10) -> (7.5, 48)
  line L11 (2.5, 10) -> (7.5, 10)
  line L12 (2.5, 48) -> (2.5, 10)
  line L13 (9.5, 57.5) -> (0.5, 0.5)
  line L14 (7.5, 10) -> (2.5, 48)
  line L15 (12.5, 10) -> (17.5, 10)
  line L16 (17.5, 10) -> (17.5, 23)
  line L17 (12.5, 23) -> (12.5, 10)
  line L18 (17.5, 23) -> (12.5, 23)
  line L19 (19.5, 32.5) -> (10.5, 0.5)
  line L20 (10.5, 0.5) -> (19.5, 0.5)
  line L21 (10.5, 32.5) -> (10.5, 0.5)
  line L22 (17.5, 10) -> (12.5, 23)
  line L23 (19.5, 32.5) -> (10.5, 32.5)
  line L24 (19.5, 0.5) -> (19.5, 32.5)
  line L25 (22, 35) -> (27, 35)
  line L26 (20, 25.5) -> (29, 25.5)
  line L27 (27, 48) -> (22, 48)
  line L28 (27, 35) -> (22, 48)
  line L29 (22, 48) -> (22, 35)
  line L30 (27, 35) -> (27, 48)
  line L31 (20, 57.5) -> (20, 25.5)
  line L32 (29, 57.5) -> (20, 25.5)
  line L33 (29, 25.5) -> (29, 57.5)
  line L34 (29, 57.5) -> (20, 57.5)
  circle C1 centre (14, 54) radius 1.625
  circle C2 centre (26, 4) radius 1.625
  point P1 (0, 0)
  point P2 (0, 0)
  point P4 (30, 58)
  point P5 (0, 58)
  point P6 (14, 54)
  point P10 (9.5, 0.5)
  point P11 (0.5, 0.5)
  point P8 (0.5, 57.5)
  point P12 (2.5, 48)
  point P15 (2.5, 10)
  point P13 (7.5, 48)
  point P7 (26, 4)
  point P16 (10.5, 0.5)
  point P17 (19.5, 0.5)
  point P19 (10.5, 32.5)
  point P22 (12.5, 23)
  point P23 (12.5, 10)
  point P20 (17.5, 23)
  point P26 (20, 25.5)
  point P28 (29, 25.5)
  point P24 (20, 57.5)
  point P25 (22, 35)
  point P27 (22, 48)
  point P29 (27, 48)
  point P31 (29, 57.5)
  horizontal L1
  vertical L2
  horizontal L8
  vertical L3
  coincident P1 P2
  equal C1 C2
  horizontal L4
  vertical L5
  horizontal L6
  vertical L7
  horizontal L9
  vertical L10
  horizontal L11
  vertical L12
  midpoint L13 L14
  horizontal L23
  vertical L24
  horizontal L20
  vertical L21
  horizontal L18
  vertical L16
  horizontal L15
  vertical L17
  midpoint L19 L22
  horizontal L34
  vertical L33
  horizontal L26
  vertical L31
  horizontal L27
  vertical L30
  horizontal L25
  vertical L29
  midpoint L28 L32
  dimension "d1" distance P4 P5 = 30
  dimension "d2" distance P2 P5 = 58
  dimension "d3" distance P6 L8 = 4
  dimension "d6" diameter C1 = 3.25
  dimension "d7" distance L3 P6 = 14
  dimension "d11" distance P10 P11 = 9
  dimension "d12" distance P8 P11 = 57
  dimension "d21" distance P12 P15 = 38
  dimension "d22" distance P12 P13 = 5
  dimension "d25" distance L1 P7 = 4
  dimension "d31" distance P16 P17 = 9
  dimension "d32" distance P16 P19 = 32
  dimension "d33" distance P22 P23 = 13
  dimension "d34" distance P20 P22 = 5
  dimension "d35" distance P8 L8 = 0.5
  dimension "d36" distance L3 P8 = 0.5
  dimension "d39" distance P26 P28 = 9
  dimension "d40" distance P24 P26 = 32
  dimension "d41" distance P25 P27 = 13
  dimension "d42" distance P27 P29 = 5
  dimension "d45" distance L24 P24 = 0.5
  dimension "d47" distance L2 P28 = 1
  dimension "d48" distance L2 P7 = 4
  dimension "d49" distance L1 P17 = 0.5
  dimension "d50" distance L8 P31 = 0.5
extrude "Extrude1" new body sketch "Sketch1" profile of L1 L2 L8 L3 C1 C2 L4 L5 L6 L7 along normal blind 1.6
extrude "Extrude2" add sketch "Sketch1" profile of L4 L5 L6 L7 L9 L10 L11 L12 L15 L16 L17 L18 L20 L21 L23 L24 L25 L26 L27 L29 L30 L31 L33 L34 along normal blind 26
extrude "Extrude3" add sketch "Sketch1" profile of L9 L10 L11 L12 L15 L16 L17 L18 L25 L27 L29 L30 against normal blind 2

design "HW_M4-Washer"
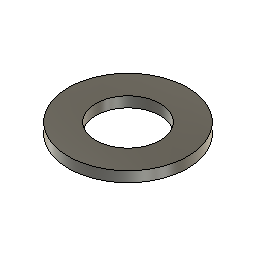
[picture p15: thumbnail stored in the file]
sketch "Sketch1" plane through (0, 0, 0) normal (0, 1, 0) x axis (1, 0, 0)
  line L1 (4, 0) -> (2.15, 0)
  line L2 (4, -0.7) -> (4, 0)
  line L3 (2.15, -0.7) -> (4, -0.7)
  line L4 (2.15, 0) -> (2.15, -0.7)
  point P1 (0, 0)
  point P2 (2.15, 0)
  point P5 (2.15, -0.7)
  horizontal L1
  vertical L2
  horizontal L3
  vertical L4
  coincident P1 L1
  dimension "d1" distance P2 P5 = 0.7
  dimension "d2" distance P1 L4 = 2.15 (= "( 4.3 / 2 ) * 1 mm")
  dimension "d3" distance P1 L2 = 4 (= "( 8 / 2 ) * 1 mm")
revolve "Revolve1" sketch "Sketch1" AlongAngle 360

design "PP_SHFT_6x200"
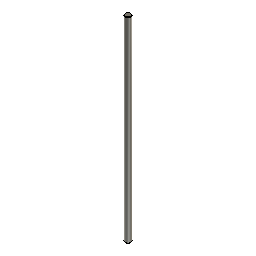
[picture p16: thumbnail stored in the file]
sketch "Sketch1" plane through (0, 0, 0) normal (0, 0, 1) x axis (1, 0, 0)
  circle C1 centre (0, 0) radius 3
  point P1 (0, 0)
  point P2 (0, 0)
  coincident P1 P2
  dimension "d1" diameter C1 = 6
extrude "Extrude1" new body sketch "Sketch1" along normal blind 200
chamfer "Chamfer1" distance 0.5

design "HW_M5x25-FHCS"
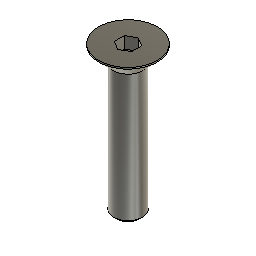
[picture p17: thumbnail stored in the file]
sketch "Sketch1" plane through (0, 0, 0) normal (0, 1, 0) x axis (1, 0, 0)
  line L1 (0, 25) -> (0, 0)
  line L2 (1.95, 25) -> (0, 25)
  line L3 (2.45, 24.5) -> (1.95, 25)
  line L4 (2.45, 2.8) -> (2.45, 24.5)
  line L5 (5, 0.25) -> (2.45, 2.8)
  line L6 (5, 0) -> (5, 0.25)
  line L7 (0, 0) -> (5, 0)
  point P1 (0, 0)
  point P2 (0, 0)
  point P9 (0, 0)
  point P3 (0, 25)
  point P4 (1.95, 25)
  point P8 (5, 0)
  point P7 (5, 0.25)
  coincident P1 P2
  vertical L1
  perpendicular L1 L2
  perpendicular L2 L4
  parallel L3 L5
  parallel L4 L6
  perpendicular L6 L7
  coincident P1 P9
  dimension "d1" distance P3 L4 = 2.45 (= "( 4.9 / 2 ) * 1 mm")
  dimension "d3" angle L2 L3 = 45
  dimension "d5" distance P4 L4 = 0.5
  dimension "d6" distance P2 P3 = 25
  dimension "d7" distance P8 P9 = 5 (= "( 10 / 2 ) * 1 mm")
  dimension "d9" distance P7 P8 = 0.25
revolve "Revolve1" sketch "Sketch1" AlongAngle 360
sketch "Sketch2" plane through (0, 0, 0) normal (0, 0, 1) x axis (-1, 0, 0)
  line L1 (0, -1.7321) -> (-1.5, -0.866)
  line L2 (1.5, -0.866) -> (0, -1.7321)
  line L3 (1.5, 0.866) -> (1.5, -0.866)
  line L4 (0, 1.7321) -> (1.5, 0.866)
  line L5 (-1.5, 0.866) -> (0, 1.7321)
  line L6 (-1.5, -0.866) -> (-1.5, 0.866)
  circle C1 centre (0, 0) radius 5
  point P1 (0, 0)
  point P9 (0, 0)
  coincident P1 P9
  vertical L6
  dimension "d12" distance L3 L6 = 3
extrude "Extrude1" cut sketch "Sketch2" profile of L1 L2 L3 L4 L5 L6 against normal blind 2

design "AS_Flanged-Idler" references "PP_BRNG_624-4x13x5", "HW_M4-Washer"
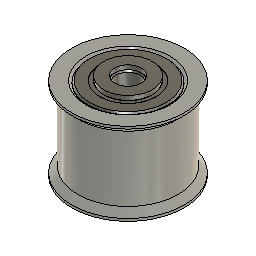
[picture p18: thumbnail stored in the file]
sketch "Sketch1" plane through (0, 0, 0) normal (0, 1, 0) x axis (1, 0, 0)
  line L1 (6.5, -4.75) -> (6.5, 0)
  line L2 (6, -5.25) -> (6.5, -4.75)
  line L3 (6, -8.25) -> (6, -5.25)
  line L4 (6.5, -8.75) -> (6, -8.25)
  line L5 (6.5, -13.5) -> (6.5, -8.75)
  line L6 (9.2, -13.5) -> (6.5, -13.5)
  line L7 (9.2, -13.1) -> (9.2, -13.5)
  line L8 (8.2, -12.1) -> (9.2, -13.1)
  line L9 (8.2, -1.4) -> (8.2, -12.1)
  line L10 (9.2, -0.4) -> (8.2, -1.4)
  line L11 (9.2, 0) -> (9.2, -0.4)
  line L12 (6.5, 0) -> (9.2, 0)
  line L13 (6.5, 0) -> (0, 0)
  line L14 (6.5, -5) -> (6.5, 0)
  line L15 (0, -5) -> (6.5, -5)
  line L16 (0, 0) -> (0, -5)
  line L17 (8.2, -6.75) -> (6, -6.75)
  line L18 (9.6, -11.75) -> (8.2, -11.75)
  line L19 (9.6, -1.75) -> (9.6, -11.75)
  line L20 (8.2, -1.75) -> (9.6, -1.75)
  line L21 (8.454, -1.75) -> (8.454, -11.75)
  line L22 (9.6, -6.75) -> (8.2, -6.75)
  point P2 (6.5, 0)
  point P14 (6.5, 0)
  point P1 (0, 0)
  point P15 (0, 0)
  point P17 (6.5, -5)
  point P19 (6, -6.75)
  point P20 (8.2, -6.75)
  point P21 (8.2, -11.75)
  point P24 (8.2, -1.75)
  point P25 (8.454, -11.75)
  point P26 (8.454, -1.75)
  point P27 (9.6, -6.75)
  point P18 (0, -5)
  point P16 (6.5, 0)
  point P3 (6.5, -4.75)
  point P10 (8.2, -12.1)
  point P11 (8.2, -1.4)
  point P12 (9.2, -0.4)
  point P13 (9.2, 0)
  point P8 (9.2, -13.5)
  point P22 (9.6, -11.75)
  point P23 (9.6, -1.75)
  vertical L1
  parallel L1 L3
  perpendicular L2 L4
  parallel L3 L5
  perpendicular L3 L6
  perpendicular L6 L7
  parallel L4 L8
  perpendicular L6 L9
  perpendicular L8 L10
  parallel L9 L11
  perpendicular L11 L12
  coincident P2 P14
  equal L1 L5
  coincident P1 L12
  horizontal L13
  vertical L14
  horizontal L15
  vertical L16
  coincident P1 P15
  coincident L5 P17
  midpoint L3 P19
  midpoint L9 P20
  perpendicular L9 L17
  equal L7 L11
  coincident L9 P21
  perpendicular L9 L18
  perpendicular L18 L19
  coincident L9 P24
  perpendicular L9 L20
  coincident L18 P25
  coincident L20 P26
  perpendicular L20 L21
  perpendicular L21 L22
  midpoint L19 P27
  dimension "d1" angle L1 L2 = 45
  dimension "d2" distance P1 L1 = 6.5 (= "( 13 / 2 ) * 1 mm")
  dimension "d3" distance P15 P18 = 5
  dimension "d4" distance P15 P16 = 6.5 (= "( 13 / 2 ) * 1 mm")
  dimension "d5" distance L3 P17 = 0.5
  dimension "d6" distance P3 L15 = 0.25
  dimension "d7" distance P10 P11 = 10.7
  dimension "d8" distance P12 P13 = 0.4
  dimension "d9" distance L9 P12 = 1
  dimension "d10" distance P3 L9 = 1.7
  dimension "d11" distance P1 L9 = 8.2
  dimension "d38" distance P8 P13 = 13.5
  dimension "d55" distance P22 P23 = 10
  dimension "d56" distance P21 P22 = 1.4
  dimension "d57" distance L9 L21 = 0.254
  dimension "d58" distance P1 L21 = 8.454
revolve "Revolve1" sketch "Sketch1" AlongAngle 360 bodies "Flanged Idler"
chamfer "Chamfer1" distance 0.4
component_from_bodies "Body->Comp"
as_built_joint "As-built1"
component_insert "Component Insert3"
joint "Assemble9" alignAngle 0 alignOffsetX 0 alignOffsetY 0 alignOffsetZ 0
component_insert "Component Insert4"
joint "Assemble10" alignAngle 0 alignOffsetX 0 alignOffsetY 0 alignOffsetZ 0
component_insert "Component Insert7"
joint "Assemble7" alignAngle 0 alignOffsetX 0 alignOffsetY 0 alignOffsetZ 0
component_insert "Component Insert8"
joint "Assemble8" alignAngle 0 alignOffsetX 0 alignOffsetY 0 alignOffsetZ 0
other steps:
base_feature "Base Feature" bodies "Flanged Idler", "FP_Flanged-Idler"
create_component "CreateComponent1"
remove_body "RemoveBody1"
joint_origin "JointOrigin1"
joint_origin "JointOrigin2"
named bodies: "Flanged Idler", "FP_Flanged-Idler"

design "PP_SWTC_Omron-SS_5_F"
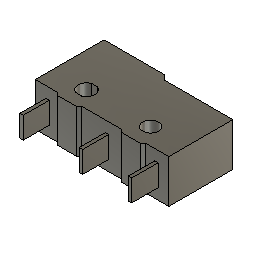
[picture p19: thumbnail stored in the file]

design "AS_YL-Giga" references "HW_M4x30-SHCS", "AS_Single-Roller", "HW_M3x10-SHCS", "HW_M4-Washer", "HW_M2x12-SHCS", "HW_M4x30-BHCS", "HW_M4x14-BHCS", "HW_M4x25-FHCS", "HW_M3-Washer", "AS_Pinched-Roller", "PP_TRNS_GT2-Pulley-20T-10mm", "HW_M4x16-SHCS", "HW_M3x10-FHCS", "HW_M4-Nylock", "PP_ACTU_N17-Stepper", "PP_SWTC_Omron-SS_5_F", "CT_UCBus-3010", "AS_Flanged-Idler"
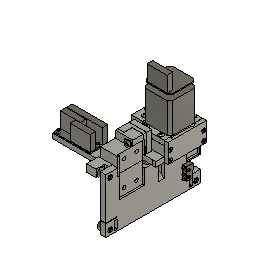
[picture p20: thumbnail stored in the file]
parameter "t_sheet_MAIN" = 9.5
parameter "extrusion_w" = 20
parameter "extrusion_h" = 20
parameter "r_cutoutTool" = 2.05 (= "4.1 mm / 2")
parameter "od_bearings" = 13
parameter "id_bearings" = 4
parameter "t_bearings" = 5
parameter "preload" = 0.15
parameter "hw_m3_thru" = 3.5
parameter "hw_m3_thread" = 2.5
parameter "hw_m3_head" = 5.5
parameter "hw_m3_headheight" = 3
parameter "hw_m3_flathead" = 6
parameter "hw_m3_buttonhead" = 5.7
parameter "hw_m3_washer" = 7
parameter "hw_m3hex_d" = 5.5
parameter "hw_m3hex_t" = 4
parameter "hw_m3i_d" = 5.4
parameter "hw_m3i_l" = 3.8
parameter "hw_m3ichamfer" = 0.95 (= "( hw_m3i_d - hw_m3_thru ) / 2")
parameter "hw_m4_thru" = 4.25
parameter "hw_m4_head" = 7
parameter "hw_m4_headheight" = 4
parameter "hw_m4hex_d" = 7
parameter "hw_m4hex_t" = 5.2
parameter "hw_m4i_d" = 6
parameter "hw_m4i_l" = 4.8
parameter "hw_m4ichamfer" = 0.875 (= "( hw_m4i_d - hw_m4_thru ) / 2")
parameter "hw_m5_thread" = 4.2
parameter "hw_m5_head" = 8.5
parameter "hw_m5_washer" = 10
parameter "hw_m5_thru" = 5.25
parameter "hw_m6_thru" = 6.5
parameter "hw_m6_head" = 10
parameter "hw_m6_flathead" = 12
parameter "hw_m6_buttonhead" = 10.5
parameter "hw_m6_washer" = 12
parameter "p_belt" = 1.4
parameter "w_belt" = 10
parameter "t_belt" = 1.4
parameter "belt_pdo_toothside" = 1.15
parameter "belt_pdo_backside" = 0.25
parameter "t_m4_washer" = 0.85
parameter "flex_t" = 2.54
parameter "flex_l" = 5
parameter "t_motor_plates" = 6 comment "5/16 Phenolic"
parameter "d650" = 1
parameter "d2043" = 10
parameter "d2164" = 7 (= "hw_m4hex_d")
